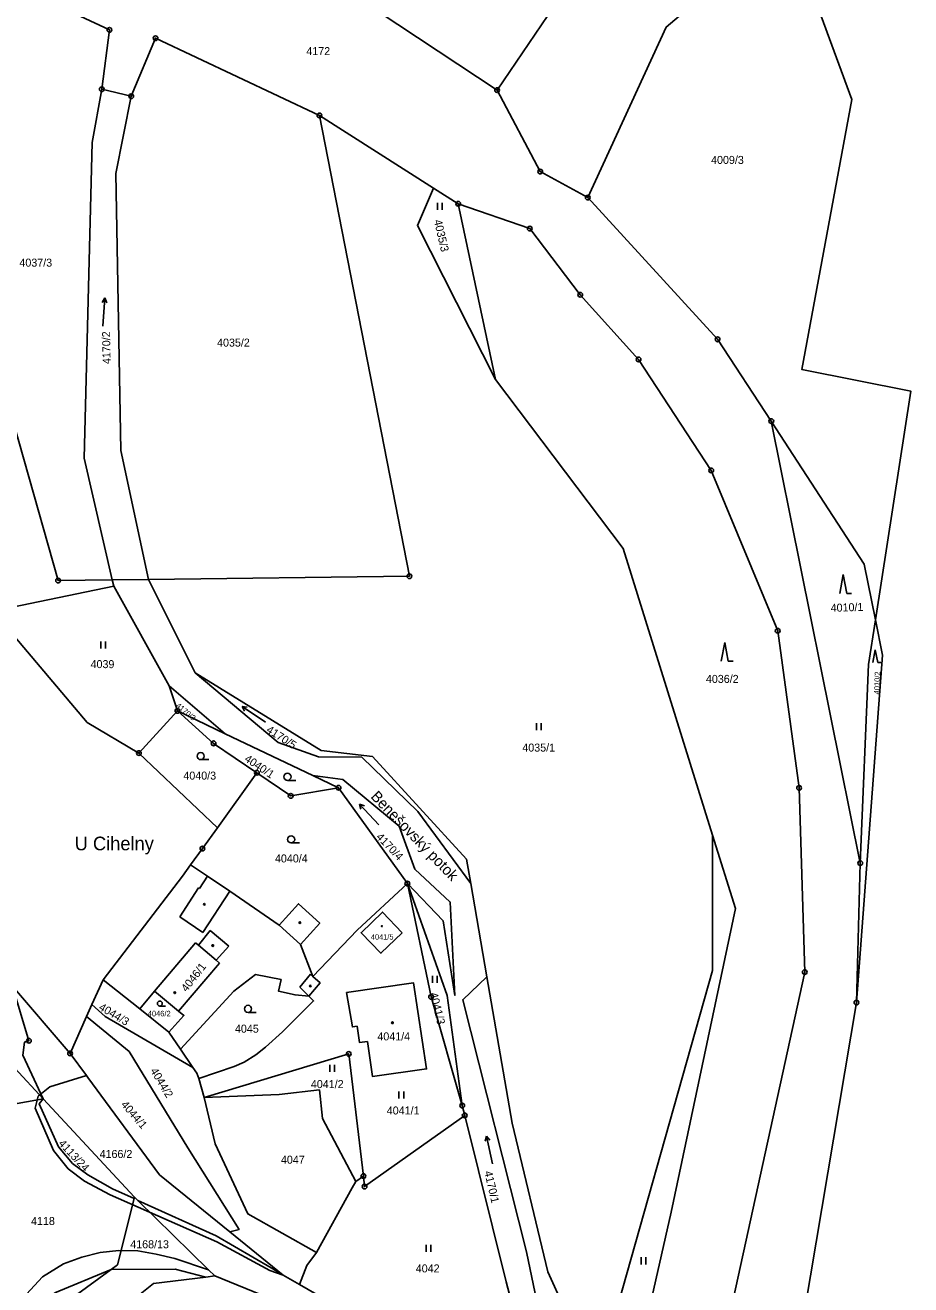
# Model space of a CAD drawing. Extents: x -733394 to -722299, y -1082822 to -1075049.
# Drawn here: x -727646.4 to -727458.2, y -1080725.9 to -1080458.3 of the extents above; entities that cross this region are included whole.
import ezdxf

# ---------------------------------------------------------------- set-up
doc = ezdxf.new("R2010")
doc.units = 0
for name, color, linetype in [('Hranice parcel', 7, 'Continuous'), ('Parcelní čísla', 7, 'Continuous'), ('Pop  PČ popisy', 7, 'Continuous'), ('Vnitřní kresba', 7, 'Continuous'), ('Značky bodu BP', 7, 'Continuous'), ('Značky budov', 7, 'Continuous'), ('Značky kultur', 7, 'Continuous')]:
    doc.layers.add(name, color=color, linetype=linetype)

msp = doc.modelspace()

# ---------------------------------------------------------------- linework, layer by layer
at = {"layer": 'Hranice parcel'}
for p, q in [((-727546.1, -1080472.1), (-727509.52, -1080418.27)), ((-727623.83, -1080473.4), (-727630.08, -1080471.9)), ((-727559.62, -1080492.89), (-727583.83, -1080477.47)), ((-727559.62, -1080492.89), (-727554.36, -1080496.24)), ((-727546.41, -1080533.54), (-727554.36, -1080496.24)), ((-727468.93, -1080636.31), (-727487.82, -1080542.41)), ((-727627.85, -1080576.14), (-727620.14, -1080576.04)), ((-727627.54, -1080577.49), (-727627.85, -1080576.14)), ((-727620.14, -1080576.04), (-727610.24, -1080595.89)), ((-727615.79, -1080598.66), (-727627.54, -1080577.49)), ((-727615.79, -1080598.66), (-727603.86, -1080608.81)), ((-727614.03, -1080603.97), (-727615.79, -1080598.66)), ((-727622.19, -1080612.93), (-727614.03, -1080603.97)), ((-727603.86, -1080608.81), (-727614.03, -1080603.97)), ((-727585.23, -1080617.69), (-727603.86, -1080608.81)), ((-727605.53, -1080628.81), (-727622.19, -1080612.93)), ((-727605.53, -1080628.81), (-727597.13, -1080617.12)), ((-727579.76, -1080620.3), (-727585.23, -1080617.69)), ((-727565.16, -1080640.66), (-727579.76, -1080620.3)), ((-727552.56, -1080635.43), (-727551.67, -1080640.62)), ((-727469.75, -1080665.92), (-727468.93, -1080636.31)), ((-727551.67, -1080640.62), (-727548.26, -1080660.48)), ((-727632.18, -1080666.36), (-727629.82, -1080661.07)), ((-727629.82, -1080661.07), (-727622.03, -1080667.26)), ((-727548.26, -1080660.48), (-727542.92, -1080691.57)), ((-727649.07, -1080662.47), (-727636.81, -1080676.74)), ((-727602.04, -1080663.51), (-727613.36, -1080675.82)), ((-727633.31, -1080668.9), (-727632.18, -1080666.36)), ((-727622.03, -1080667.26), (-727615.82, -1080672.2)), ((-727636.81, -1080676.74), (-727633.31, -1080668.9)), ((-727615.82, -1080672.2), (-727613.36, -1080675.82)), ((-727613.36, -1080675.82), (-727610.74, -1080679.69)), ((-727610.74, -1080679.69), (-727609.91, -1080680.91)), ((-727609.91, -1080680.91), (-727609.46, -1080682.04)), ((-727609.46, -1080682.04), (-727608.33, -1080686.08)), ((-727655.59, -1080688.67), (-727642.52, -1080686.38)), ((-727623.15, -1080707.24), (-727642.52, -1080686.38)), ((-727553.5, -1080687.82), (-727552.98, -1080689.89)), ((-727576.13, -1080703.93), (-727574.5, -1080702.77)), ((-727623.24, -1080707.58), (-727623.15, -1080707.24)), ((-727623.15, -1080707.24), (-727622.45, -1080707.94)), ((-727591.53, -1080723.82), (-727602.91, -1080714.61)), ((-727584.48, -1080719), (-727586.52, -1080721.8)), ((-727635.94, -1080728.37), (-727628.11, -1080722.63)), ((-727586.52, -1080721.8), (-727588.05, -1080725.83)), ((-727607.96, -1080724.23), (-727606.06, -1080724)), ((-727588.05, -1080725.83), (-727591.53, -1080723.82))]:
    msp.add_line(p, q, dxfattribs=at)
for points in [[(-727608.42, -1080431.01), (-727611.33, -1080438.83), (-727575.52, -1080452.58), (-727546.1, -1080472.1)], [(-727495.46, -1080446.18), (-727510.2, -1080458.69), (-727526.84, -1080494.92)], [(-727465.7, -1080584.62), (-727458.18, -1080536.02), (-727481.36, -1080531.44), (-727470.71, -1080474.07), (-727477.74, -1080455.04), (-727495.46, -1080446.18)], [(-727630.08, -1080471.9), (-727628.47, -1080459.29), (-727647.14, -1080450.53)], [(-727583.83, -1080477.47), (-727618.66, -1080461.07), (-727623.83, -1080473.4)], [(-727627.85, -1080576.14), (-727633.83, -1080550.3), (-727632.11, -1080483.22), (-727630.08, -1080471.9)], [(-727623.83, -1080473.4), (-727627.11, -1080489.78), (-727626.01, -1080548.63), (-727620.14, -1080576.04)], [(-727526.84, -1080494.92), (-727536.92, -1080489.41), (-727546.1, -1080472.1)], [(-727620.14, -1080576.04), (-727564.73, -1080575.35), (-727583.83, -1080477.47)], [(-727627.85, -1080576.14), (-727639.37, -1080576.28), (-727654.04, -1080524.73), (-727654.33, -1080490.37)], [(-727546.41, -1080533.54), (-727563.01, -1080500.88), (-727559.62, -1080492.89)], [(-727487.82, -1080542.41), (-727499.23, -1080525.03), (-727526.84, -1080494.92)], [(-727554.36, -1080496.24), (-727539.14, -1080501.52), (-727528.41, -1080515.56), (-727516.03, -1080529.31), (-727500.6, -1080552.88), (-727486.47, -1080586.95), (-727481.92, -1080620.34), (-727480.72, -1080659.44)], [(-727500.29, -1080630.33), (-727519.27, -1080569.47), (-727546.41, -1080533.54)], [(-727487.82, -1080542.41), (-727468.06, -1080572.77), (-727465.7, -1080584.62)], [(-727622.19, -1080612.93), (-727633.23, -1080606.43), (-727653.22, -1080582.79), (-727627.54, -1080577.49)], [(-727465.7, -1080584.62), (-727464.2, -1080592.13), (-727469.75, -1080665.92)], [(-727468.93, -1080636.31), (-727467.16, -1080594.08), (-727465.7, -1080584.62)], [(-727610.24, -1080595.89), (-727583.45, -1080612.39), (-727572.54, -1080613.67), (-727552.56, -1080635.43)], [(-727551.67, -1080640.62), (-727562.9, -1080625.35), (-727574.86, -1080613.8), (-727584.01, -1080613.71), (-727592.58, -1080610.68), (-727610.24, -1080595.89)], [(-727614.03, -1080603.97), (-727606.32, -1080610.86), (-727597.13, -1080617.12)], [(-727597.13, -1080617.12), (-727589.95, -1080622.01), (-727579.76, -1080620.3)], [(-727585.23, -1080617.69), (-727578.9, -1080618.55), (-727566.88, -1080628.44), (-727563.57, -1080637.57), (-727556.06, -1080644.59), (-727555.07, -1080664.42), (-727557.57, -1080648.59), (-727565.16, -1080640.66)], [(-727611.21, -1080636.67), (-727608.7, -1080633.22), (-727605.53, -1080628.81)], [(-727524.88, -1080746.04), (-727500.29, -1080659.09), (-727500.29, -1080630.33)], [(-727519.76, -1080757.31), (-727509.09, -1080710.48), (-727495.43, -1080645.91), (-727500.29, -1080630.33)], [(-727629.82, -1080661.07), (-727612.93, -1080639.05), (-727611.21, -1080636.67)], [(-727585.21, -1080660.41), (-727587.84, -1080653.56), (-727583.77, -1080649.03), (-727588.3, -1080644.95), (-727592.41, -1080649.51), (-727602.85, -1080642.29), (-727607.64, -1080639.07), (-727611.21, -1080636.67)], [(-727585.21, -1080660.41), (-727575.8, -1080650.57), (-727565.16, -1080640.66)], [(-727565.16, -1080640.66), (-727560.11, -1080664.73), (-727553.5, -1080687.82)], [(-727553.5, -1080687.82), (-727556.67, -1080664.43), (-727565.16, -1080640.66)], [(-727642.52, -1080686.38), (-727660.7, -1080666.8), (-727662.63, -1080664.55), (-727677.46, -1080647.25)], [(-727566.23, -1080651.14), (-727570.76, -1080655.46), (-727575, -1080651.09), (-727570.46, -1080646.7), (-727566.23, -1080651.14)], [(-727586.06, -1080664.54), (-727589.01, -1080664.29), (-727592.53, -1080663.53), (-727591.99, -1080661.05), (-727597.44, -1080659.98), (-727602.04, -1080663.51)], [(-727586.06, -1080664.54), (-727583.71, -1080661.76), (-727585.21, -1080660.41)], [(-727573.62, -1080674.2), (-727575.32, -1080674.43), (-727575.85, -1080670.95), (-727576.84, -1080671.11), (-727578.08, -1080663.79), (-727563.82, -1080661.76), (-727561.08, -1080680.01), (-727572.54, -1080681.66), (-727573.62, -1080674.2)], [(-727529.09, -1080759.4), (-727531.74, -1080757.69), (-727539.81, -1080718.88), (-727553.38, -1080665.31), (-727548.26, -1080660.48)], [(-727480.72, -1080659.44), (-727499.01, -1080743.24), (-727501.15, -1080779.47), (-727498, -1080804.36)], [(-727642.52, -1080686.38), (-727646.88, -1080677.07), (-727646.51, -1080674.33), (-727645.56, -1080674.05), (-727649.07, -1080662.47)], [(-727622.03, -1080667.26), (-727618.9, -1080663.48), (-727613.77, -1080667.72), (-727612.65, -1080668.64), (-727615.82, -1080672.2)], [(-727609.46, -1080682.04), (-727601.96, -1080679.49), (-727599.82, -1080678.62), (-727597.37, -1080677.06), (-727595.27, -1080675.39), (-727591.72, -1080672.12), (-727585.09, -1080665.57), (-727586.06, -1080664.54)], [(-727610.74, -1080679.69), (-727629.34, -1080668.85), (-727632.18, -1080666.36)], [(-727473.13, -1080824.97), (-727483.16, -1080745.84), (-727469.75, -1080665.92)], [(-727602.91, -1080714.61), (-727600.9, -1080714.11), (-727611.78, -1080696.76), (-727624.29, -1080676.31), (-727633.31, -1080668.9)], [(-727602.91, -1080714.61), (-727617.81, -1080702.55), (-727633.05, -1080681.85), (-727633.34, -1080681.45), (-727636.81, -1080676.74)], [(-727608.33, -1080686.08), (-727577.62, -1080676.84), (-727574.5, -1080702.77)], [(-727576.13, -1080703.93), (-727583.16, -1080690.55), (-727583.83, -1080684.48), (-727592.42, -1080685.43), (-727608.33, -1080686.08)], [(-727642.52, -1080686.38), (-727643.42, -1080687.43), (-727639.28, -1080696.59), (-727636.29, -1080700.08), (-727633.02, -1080702.49), (-727627.79, -1080705.52), (-727623.24, -1080707.58)], [(-727608.33, -1080686.08), (-727605.98, -1080695.9), (-727599.06, -1080710.82), (-727584.48, -1080719)], [(-727552.98, -1080689.89), (-727574.25, -1080705), (-727574.5, -1080702.77)], [(-727534.92, -1080760.31), (-727544.14, -1080725.27), (-727552.98, -1080689.89)], [(-727542.92, -1080691.57), (-727535.3, -1080723.13), (-727524.88, -1080746.04)], [(-727584.48, -1080719), (-727576.86, -1080705.25), (-727576.13, -1080703.93)], [(-727628.11, -1080722.63), (-727626.74, -1080721.63), (-727623.24, -1080707.58)], [(-727622.45, -1080707.94), (-727605.8, -1080715.46), (-727594.07, -1080722.27), (-727591.53, -1080723.82)], [(-727606.06, -1080724), (-727607.38, -1080722.7), (-727622.45, -1080707.94)], [(-727628.11, -1080722.63), (-727640.04, -1080727.58), (-727643.45, -1080731.86)], [(-727607.96, -1080724.23), (-727614.5, -1080722.58), (-727628.11, -1080722.63)], [(-727638.56, -1080741.16), (-727619.07, -1080725.61), (-727607.96, -1080724.23)], [(-727606.06, -1080724), (-727594.79, -1080728.6), (-727577.51, -1080738.45), (-727560.44, -1080749.1), (-727530.47, -1080770.23)], [(-727588.05, -1080725.83), (-727574.17, -1080733.82), (-727556.88, -1080744.57), (-727534.92, -1080760.31)]]:
    msp.add_lwpolyline(points, dxfattribs=at)
at = {"layer": 'Vnitřní kresba'}
for p, q in [((-727609.35, -1080641.68), (-727607.64, -1080639.07)), ((-727613.54, -1080647.68), (-727609.52, -1080641.57)), ((-727609.52, -1080641.57), (-727609.35, -1080641.68)), ((-727602.85, -1080642.29), (-727608.6, -1080651.07)), ((-727608.6, -1080651.07), (-727613.54, -1080647.68)), ((-727609.55, -1080653.76), (-727607.09, -1080650.65)), ((-727607.09, -1080650.65), (-727603.09, -1080653.96)), ((-727587.84, -1080653.56), (-727592.41, -1080649.51)), ((-727618.9, -1080663.48), (-727610.21, -1080653.21)), ((-727610.21, -1080653.21), (-727609.55, -1080653.76)), ((-727609.55, -1080653.76), (-727605.78, -1080656.93)), ((-727603.09, -1080653.96), (-727605.78, -1080656.93)), ((-727605.11, -1080657.54), (-727613.77, -1080667.72)), ((-727605.78, -1080656.93), (-727605.11, -1080657.54)), ((-727585.77, -1080659.87), (-727588.03, -1080662.65)), ((-727585.21, -1080660.41), (-727585.77, -1080659.87)), ((-727588.03, -1080662.65), (-727586.06, -1080664.54)), ((-727641.16, -1080683.84), (-727633.34, -1080681.45)), ((-727643.6, -1080685.81), (-727644.22, -1080688.39)), ((-727643.6, -1080685.81), (-727641.16, -1080683.84)), ((-727644.22, -1080688.39), (-727640.38, -1080697.37)), ((-727640.38, -1080697.37), (-727637.23, -1080701.28)), ((-727637.23, -1080701.28), (-727633.73, -1080703.85)), ((-727633.73, -1080703.85), (-727628.28, -1080706.76)), ((-727628.28, -1080706.76), (-727605.63, -1080716.78)), ((-727605.63, -1080716.78), (-727594.39, -1080722.86)), ((-727638.19, -1080721.42), (-727634.32, -1080720.02)), ((-727634.32, -1080720.02), (-727630.43, -1080719.02)), ((-727630.43, -1080719.02), (-727626.46, -1080718.57)), ((-727626.46, -1080718.57), (-727622.45, -1080718.63)), ((-727622.45, -1080718.63), (-727618.51, -1080719.35)), ((-727618.51, -1080719.35), (-727614.6, -1080720.29)), ((-727614.6, -1080720.29), (-727607.38, -1080722.7)), ((-727642.7, -1080724.2), (-727638.19, -1080721.42)), ((-727594.39, -1080722.86), (-727591.53, -1080723.82)), ((-727649.53, -1080731.62), (-727642.7, -1080724.2))]:
    msp.add_line(p, q, dxfattribs=at)
at = {"layer": 'Značky bodu BP'}
for centre, radius in [((-727628.47, -1080459.29), 0.5), ((-727628.47, -1080459.29), 0.0303), ((-727618.66, -1080461.07), 0.5), ((-727618.66, -1080461.07), 0.0303), ((-727630.08, -1080471.9), 0.5), ((-727630.08, -1080471.9), 0.0303), ((-727546.1, -1080472.1), 0.5), ((-727623.83, -1080473.4), 0.5), ((-727623.83, -1080473.4), 0.0303), ((-727546.1, -1080472.1), 0.0303), ((-727583.83, -1080477.47), 0.5), ((-727583.83, -1080477.47), 0.0303), ((-727536.92, -1080489.41), 0.5), ((-727536.92, -1080489.41), 0.0303), ((-727554.36, -1080496.24), 0.5), ((-727526.84, -1080494.92), 0.5), ((-727526.84, -1080494.92), 0.0303), ((-727554.36, -1080496.24), 0.0303), ((-727539.14, -1080501.52), 0.5), ((-727539.14, -1080501.52), 0.0303), ((-727528.41, -1080515.56), 0.5), ((-727528.41, -1080515.56), 0.0303), ((-727499.23, -1080525.03), 0.5), ((-727499.23, -1080525.03), 0.0303), ((-727516.03, -1080529.31), 0.5), ((-727516.03, -1080529.31), 0.0303), ((-727487.82, -1080542.41), 0.5), ((-727487.82, -1080542.41), 0.0303), ((-727500.6, -1080552.88), 0.5), ((-727500.6, -1080552.88), 0.0303), ((-727639.37, -1080576.28), 0.5), ((-727639.37, -1080576.28), 0.0303), ((-727564.73, -1080575.35), 0.5), ((-727564.73, -1080575.35), 0.0303), ((-727486.47, -1080586.95), 0.5), ((-727486.47, -1080586.95), 0.0303), ((-727614.03, -1080603.97), 0.5), ((-727614.03, -1080603.97), 0.0303), ((-727606.32, -1080610.86), 0.5), ((-727606.32, -1080610.86), 0.0303), ((-727622.19, -1080612.93), 0.5), ((-727622.19, -1080612.93), 0.0303), ((-727597.13, -1080617.12), 0.5), ((-727597.13, -1080617.12), 0.0303), ((-727589.95, -1080622.01), 0.5), ((-727579.76, -1080620.3), 0.5), ((-727579.76, -1080620.3), 0.0303), ((-727481.92, -1080620.34), 0.5), ((-727481.92, -1080620.34), 0.0303), ((-727589.95, -1080622.01), 0.0303), ((-727608.7, -1080633.22), 0.5), ((-727608.7, -1080633.22), 0.0303), ((-727468.93, -1080636.31), 0.5), ((-727468.93, -1080636.31), 0.0303), ((-727565.16, -1080640.66), 0.5), ((-727565.16, -1080640.66), 0.0303), ((-727480.72, -1080659.44), 0.5), ((-727480.72, -1080659.44), 0.0303), ((-727560.11, -1080664.73), 0.5), ((-727560.11, -1080664.73), 0.0303), ((-727469.75, -1080665.92), 0.5), ((-727469.75, -1080665.92), 0.0303), ((-727645.56, -1080674.05), 0.5), ((-727645.56, -1080674.05), 0.0303), ((-727636.81, -1080676.74), 0.5), ((-727636.81, -1080676.74), 0.0303), ((-727577.62, -1080676.84), 0.5), ((-727577.62, -1080676.84), 0.0303), ((-727553.5, -1080687.82), 0.5), ((-727553.5, -1080687.82), 0.0303), ((-727552.98, -1080689.89), 0.5), ((-727552.98, -1080689.89), 0.0303), ((-727574.5, -1080702.77), 0.5), ((-727574.25, -1080705), 0.5), ((-727574.5, -1080702.77), 0.0303), ((-727574.25, -1080705), 0.0303)]:
    msp.add_circle(centre, radius, dxfattribs=at)
at = {"layer": 'Značky budov'}
for centre, radius in [((-727608.31, -1080645.04), 0.175), ((-727588, -1080648.95), 0.175), ((-727570.57, -1080649.7), 0.117), ((-727606.51, -1080653.82), 0.175), ((-727614.57, -1080663.83), 0.175), ((-727585.78, -1080662.39), 0.175), ((-727568.32, -1080670.22), 0.175)]:
    msp.add_circle(centre, radius, dxfattribs=at)
at = {"layer": 'Značky kultur'}
for p, q in [((-727558.76, -1080497.53), (-727558.76, -1080496.03)), ((-727557.76, -1080497.53), (-727557.76, -1080496.03)), ((-727629.46, -1080516.25), (-727630.03, -1080517.19)), ((-727629.88, -1080522.24), (-727629.46, -1080516.25)), ((-727629.46, -1080516.25), (-727629.03, -1080517.26)), ((-727472.52, -1080575.02), (-727473.27, -1080579.02)), ((-727471.77, -1080579.02), (-727472.52, -1080575.02)), ((-727471.77, -1080579.02), (-727470.77, -1080579.02)), ((-727630.27, -1080590.7), (-727630.27, -1080589.2)), ((-727629.27, -1080590.7), (-727629.27, -1080589.2)), ((-727497.71, -1080589.43), (-727498.46, -1080593.43)), ((-727496.96, -1080593.43), (-727497.71, -1080589.43)), ((-727465.72, -1080591.02), (-727466.22, -1080593.7)), ((-727465.22, -1080593.7), (-727465.72, -1080591.02)), ((-727496.96, -1080593.43), (-727495.96, -1080593.43)), ((-727465.22, -1080593.7), (-727464.55, -1080593.7)), ((-727595.31, -1080606.39), (-727600.29, -1080603.04)), ((-727600.29, -1080603.04), (-727599.76, -1080604)), ((-727600.29, -1080603.04), (-727599.2, -1080603.17)), ((-727537.7, -1080608.05), (-727537.7, -1080606.55)), ((-727536.7, -1080608.05), (-727536.7, -1080606.55)), ((-727609.07, -1080614.32), (-727607.32, -1080614.32)), ((-727590.63, -1080618.72), (-727588.88, -1080618.72)), ((-727571.24, -1080628.16), (-727575.33, -1080623.77)), ((-727575.33, -1080623.77), (-727575.03, -1080624.82)), ((-727575.33, -1080623.77), (-727574.3, -1080624.14)), ((-727589.85, -1080632.01), (-727588.1, -1080632.01)), ((-727559.81, -1080661.75), (-727559.81, -1080660.25)), ((-727558.81, -1080661.75), (-727558.81, -1080660.25)), ((-727617.75, -1080666.67), (-727616.52, -1080666.67)), ((-727599.02, -1080668.01), (-727597.27, -1080668.01)), ((-727581.62, -1080680.67), (-727581.62, -1080679.17)), ((-727580.62, -1080680.67), (-727580.62, -1080679.17)), ((-727566.94, -1080686.34), (-727566.94, -1080684.84)), ((-727565.94, -1080686.34), (-727565.94, -1080684.84)), ((-727548.31, -1080694.28), (-727548.6, -1080695.34)), ((-727547.06, -1080700.15), (-727548.31, -1080694.28)), ((-727548.31, -1080694.28), (-727547.61, -1080695.13)), ((-727561.16, -1080718.91), (-727561.16, -1080717.41)), ((-727560.16, -1080718.91), (-727560.16, -1080717.41)), ((-727515.46, -1080721.54), (-727515.46, -1080720.04)), ((-727514.46, -1080721.54), (-727514.46, -1080720.04))]:
    msp.add_line(p, q, dxfattribs=at)
for centre, radius in [((-727609.07, -1080613.57), 0.75), ((-727590.63, -1080617.97), 0.75), ((-727589.85, -1080631.26), 0.75), ((-727617.75, -1080666.14), 0.525), ((-727599.02, -1080667.26), 0.75)]:
    msp.add_circle(centre, radius, dxfattribs=at)

# ---------------------------------------------------------------- texts
at = {"layer": 'Parcelní čísla'}
for s, height, p in [('4172', 1.7, (-727586.62, -1080464.66)), ('4009/3', 1.7, (-727500.62, -1080487.77)), ('4037/3', 1.7, (-727647.59, -1080509.59)), ('4035/2', 1.7, (-727605.59, -1080526.58)), ('4039', 1.7, (-727632.47, -1080594.88)), ('4036/2', 1.7, (-727501.72, -1080598.02)), ('4035/1', 1.7, (-727540.73, -1080612.61)), ('4040/3', 1.7, (-727612.75, -1080618.56)), ('4040/4', 1.7, (-727593.29, -1080636.16)), ('4041/5', 1.139, (-727572.91, -1080652.55)), ('4046/2', 1.19, (-727620.32, -1080668.86)), ('4045', 1.7, (-727601.79, -1080672.32)), ('4041/4', 1.7, (-727571.53, -1080673.96)), ('4041/2', 1.7, (-727585.66, -1080684.09)), ('4041/1', 1.7, (-727569.53, -1080689.7)), ('4166/2', 1.7, (-727630.55, -1080698.94)), ('4047', 1.7, (-727592.02, -1080700.15)), ('4118', 1.7, (-727645.12, -1080713.18)), ('4168/13', 1.7, (-727624.04, -1080718.12)), ('4042', 1.7, (-727563.37, -1080723.25))]:
    msp.add_text(s, height=height, dxfattribs=at).set_placement(p)
for s, height, rotation, p in [('4035/3', 1.7, 283, (-727559.52, -1080499.8)), ('4170/2', 1.7, 91, (-727628.21, -1080530.28)), ('4010/1', 1.7, 2, (-727475.18, -1080582.95)), ('4010/2', 1.19, 88, (-727464.82, -1080600.47)), ('4170/3', 1.14, 320, (-727614.41, -1080603.01)), ('4170/5', 1.7, 327, (-727595.28, -1080608.37)), ('4040/1', 1.7, 326, (-727599.93, -1080614.52)), ('4170/4', 1.7, 314, (-727571.91, -1080630.87)), ('4046/1', 1.7, 52, (-727612.07, -1080663.79)), ('4041/3', 1.7, 284, (-727560.41, -1080664)), ('4044/3', 1.7, 329, (-727630.88, -1080667.35)), ('4044/2', 1.7, 301, (-727619.85, -1080680.39)), ('4044/1', 1.7, 311, (-727626.12, -1080687.68)), ('4113/24', 1.7, 313, (-727639.42, -1080695.97)), ('4170/1', 1.7, 283, (-727548.82, -1080701.88))]:
    msp.add_text(s, height=height, rotation=rotation, dxfattribs=at).set_placement(p)
at = {"layer": 'Pop  PČ popisy'}
msp.add_text('Benešovský potok', height=2.3, rotation=314, dxfattribs=at).set_placement((-727573.09, -1080622.31))
msp.add_text('U Cihelny', height=2.9, dxfattribs=at).set_placement((-727635.84, -1080633.58))

doc.saveas('drawing.dxf')
